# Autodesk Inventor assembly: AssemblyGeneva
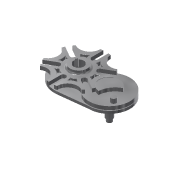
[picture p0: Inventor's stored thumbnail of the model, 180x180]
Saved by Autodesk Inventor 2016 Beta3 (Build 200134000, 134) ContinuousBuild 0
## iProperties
Created: 2016-03
Part Number: AssemblyGeneva
Document SubType Name: Assembly
Designer: Gaurav
Author: Gaurav
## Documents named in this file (5)
- D:\My Data\Books_Final Books\Autodesk Inventor 2015_resources\Chapter 7\geneva-drive\AssemblyGeneva.iam
- D:\My Data\Books_Final Books\Autodesk Inventor 2015_resources\Chapter 7\geneva-drive\Base.ipt
- D:\My Data\Books_Final Books\Autodesk Inventor 2015_resources\Chapter 7\geneva-drive\Impulsor.ipt
- D:\My Data\Books_Final Books\Autodesk Inventor 2015_resources\Chapter 7\geneva-drive\Rotor.ipt
- D:\My Data\Books_Final Books\Autodesk Inventor 2015_resources\Chapter 7\geneva-drive\Pin.ipt
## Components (4 placed, 4 different names)
1. Base:1 — Rotational:1, Rotational:2
2. Impulsor:1 — Rotational:1, Rigid:1
3. Rotor:1 — Rotational:2
4. Pin:1 — Rigid:1
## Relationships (3: RevoluteJoint 2, WeldJoint 1)
- Rotational:1 [RevoluteJoint]: Base:1 ↔ Impulsor:1
- Rotational:2 [RevoluteJoint]: Base:1 ↔ Rotor:1
- Rigid:1 [WeldJoint]: Impulsor:1 ↔ Pin:1
